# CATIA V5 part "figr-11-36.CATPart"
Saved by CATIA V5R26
Part number: Part1
Bounding box of the stored display mesh (mm): x -55 to 66, y -170 to 170, z -50 to 0
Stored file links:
  D:\_Deepak\CATIA\CATIA V5-6R2016_Deepak\Resources\Part files\Partfiles\c11_catia_v5_6r2016_prt\figr-11-36.CATPart
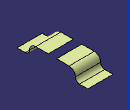
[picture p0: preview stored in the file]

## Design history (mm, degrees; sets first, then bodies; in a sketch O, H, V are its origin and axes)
Set1
  Extrude1: Element1 Sketch1, Lim1 66, Lim2 55, Direction yz-plane
  Symmetry1: ToTransfor Extrude1, Reference zx-plane
Body1 (main body)
  Sketch1 on yz-plane, origin (0, 0, 0), H (0, 1, 0), V (0, 0, 1)
    point P1 (20, 0)
    line L1 (20, 0) -> (80, 0)
    arc A1 centre (80, -30) radius 30 from (80, 0) to (110, -30) cw
    arc A2 centre (130, -30) radius 20 from (110, -30) to (130, -50) ccw
    line L2 (130, -50) -> (170, -50)
    coincidence: P1 H
    horizontal: L1 H
    tangency: A1 L1, A2 A1, L2 A2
